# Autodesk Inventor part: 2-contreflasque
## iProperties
Created: 2011-02
Part Number: 2-contreflasque
Document SubType Name: Modeling
Designer: eric
Density: 1 g/cm^3
Author: eric
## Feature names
1. Base1
